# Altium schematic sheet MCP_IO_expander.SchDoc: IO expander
size A4; Project: STM32MP15x-EVAL; Date: Not used; ApprovedBy: Not used; CheckedBy: Not used; Author: Not used; CompanyName: STMicroelectronics; DrawnBy: Not used; Engineer: Not used; Organization: Not used; Address1: Not used; Address2: Not used; Address3: Not used; Address4: Not used; DocumentNumber: 16; Revision: Not used; SheetNumber: 16; SheetTotal: 17
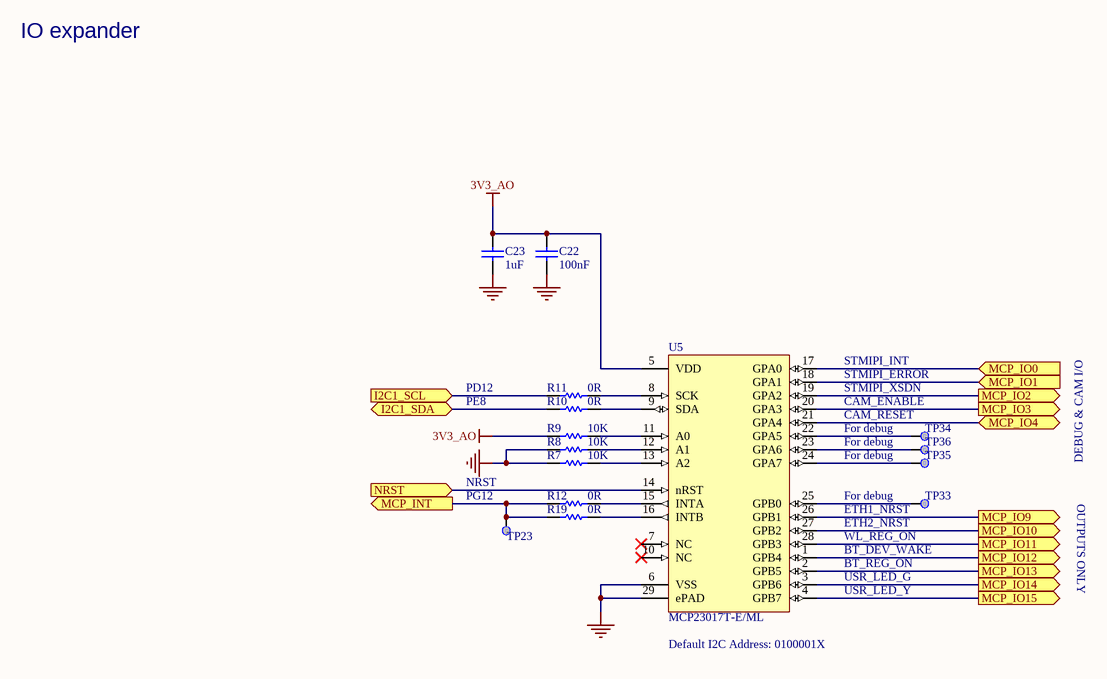
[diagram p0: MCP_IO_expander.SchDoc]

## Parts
C22  value 100nF  [C0402]  (hidden comment: Capacitor)
C23  value 1uF  [C0201_MURATA_GRM033_H0P3]  (hidden comment: Capacitor)
R7  value 10K  [R0402]  (hidden comment: Resistor)
R8  value 10K  [R0402]  (hidden comment: Resistor)
R9  value 10K  [R0402]  (hidden comment: Resistor)
R10  value 0R  [R0402]  (hidden comment: Resistor)
R11  value 0R  [R0402]  (hidden comment: Resistor)
R12  value 0R  [R0402]  (hidden comment: Resistor)
R19  value 0R  [R0402]  (hidden comment: Resistor)
TP23  Test Point  [TP_SMD_1MM]  (value not drawn)  (no BOM)
TP33  Test Point  [TP_SMD_1MM]  (value not drawn)  (no BOM)
TP34  Test Point  [TP_SMD_1MM]  (value not drawn)  (no BOM)
TP35  Test Point  [TP_SMD_1MM]  (value not drawn)  (no BOM)
TP36  Test Point  [TP_SMD_1MM]  (value not drawn)  (no BOM)
U5  value MCP23017T-E/ML  [ICC_QFN28-EPAD_6X6_P065]  (hidden comment: MCP23017)

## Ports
I2C1_SCL (in), I2C1_SDA (bidir), MCP_INT (out), MCP_IO0 (in), MCP_IO1 (in), MCP_IO2 (out), MCP_IO3 (out), MCP_IO4 (bidir), MCP_IO9 (out), MCP_IO10 (out), MCP_IO11 (out), MCP_IO12 (out), MCP_IO13 (out), MCP_IO14 (out), MCP_IO15 (out), NRST (in)

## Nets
3V3_AO: C22.2 C23.2 R9.1 U5.5(VDD)
GND: C22.1 C23.1 R7.1 R8.1 U5.6(VSS) U5.29(ePAD)
I2C1_SCL: R11.1 ; port I2C1_SCL
I2C1_SDA: R10.1 ; port I2C1_SDA
MCP_INT: R12.1 R19.1 TP23.1 ; port MCP_INT
MCP_IO0: U5.17(GPA0) ; port MCP_IO0
MCP_IO1: U5.18(GPA1) ; port MCP_IO1
MCP_IO2: U5.19(GPA2) ; port MCP_IO2
MCP_IO3: U5.20(GPA3) ; port MCP_IO3
MCP_IO4: U5.21(GPA4) ; port MCP_IO4
MCP_IO9: U5.26(GPB1) ; port MCP_IO9
MCP_IO10: U5.27(GPB2) ; port MCP_IO10
MCP_IO11: U5.28(GPB3) ; port MCP_IO11
MCP_IO12: U5.1(GPB4) ; port MCP_IO12
MCP_IO13: U5.2(GPB5) ; port MCP_IO13
MCP_IO14: U5.3(GPB6) ; port MCP_IO14
MCP_IO15: U5.4(GPB7) ; port MCP_IO15
NRST: U5.14(nRST) ; port NRST
NetR7_2: R7.2 U5.13(A2)
NetR8_2: R8.2 U5.12(A1)
NetR9_2: R9.2 U5.11(A0)
NetR10_2: R10.2 U5.9(SDA)
NetR11_2: R11.2 U5.8(SCK)
NetR12_2: R12.2 U5.15(INTA)
NetR19_2: R19.2 U5.16(INTB)
NetTP33_1: TP33.1 U5.25(GPB0)
NetTP34_1: TP34.1 U5.22(GPA5)
NetTP35_1: TP35.1 U5.24(GPA7)
NetTP36_1: TP36.1 U5.23(GPA6)

Not connected (* = marked no-connect by the designer): U5 7(NC)* 10(NC)*

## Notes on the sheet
- IO expander
- STMIPI_INT
- STMIPI_ERROR
- PD12
- PE8
- CAM_RESET
- For debug
- CAM_ENABLE
- STMIPI_XSDN
- (near TP23) PG12
- (near TP23) NRST
- (near TP33) ETH1_NRST
- OUTPUTS ONLY
- DEBUG & CAM I/O
- BT_DEV_WAKE
- BT_REG_ON
- (near TP33) ETH2_NRST
- WL_REG_ON
- USR_LED_G
- (near U5) Default I2C Address: 0100001X
- USR_LED_Y

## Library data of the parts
C22 = MCD-00006: Capacitor, MLCC, 100nF, 16V, X7R, +/-10%, 0402, T=0.5mm; Part_Preference: Recommended; Manufacturer: YAGEO; Manufacturer_Part_Number: CC0402KRX7R7BB104; Partial_Alternate_Internal_Part_Number: MCD-03299; Order_Code_RS: 9402047; Component_Country_Of_Origin: China; ShowFields: YES; ID: 2474
C23 = MCD-02377: Capacitor, MLCC, 1uF, 6.3V, X5R, +/-20%, 0201, T=0,3mm; Part_Preference: Recommended; Manufacturer: MURATA; Manufacturer_Part_Number: GRM033R60J105MEA2; Partial_Alternate_Internal_Part_Number: MCD-04356; Order_Code_RS: 820-0643; Component_Country_Of_Origin: Japan°; ShowFields: YES; ID: 4483
R7-R9 = MCD-00053: Resistor, 10K, 0402, +/-1%, 1/16W; BMS_Part_Number: 9131590; Part_Preference: Recommended; Manufacturer: YAGEO; Manufacturer_Part_Number: RC0402FR-0710KL; Order_Code_RS: 9239359; Component_Country_Of_Origin: China; ShowFields: YES; ID: 2539
R10-R12 R19 = MCD-00052: Resistor, 0R, 0402, +/-5%, 1/16W; Part_Preference: Recommended; Manufacturer: YAGEO; Manufacturer_Part_Number: RC0402JR-070RL; Order_Code_RS: 9232516RL; Component_Country_Of_Origin: China; ShowFields: YES; ID: 2540
TP23 TP33-TP36 = MCD-00074: Test Point 1mm; Part_Type: Misc; Part_Preference: Recommended; ShowFields: YES; ID: 2518; Component_Country_Of_Origin: Unknown
U5 = MCD-02210: 16-bit port expander with I2C control; Part_Preference: Recommended; Part_Type: IC; Manufacturer: MICROCHIP; Order_code_RS: 177-2846; Component_Country_Of_Origin: Unknown; ShowFields: YES; ID: 4310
